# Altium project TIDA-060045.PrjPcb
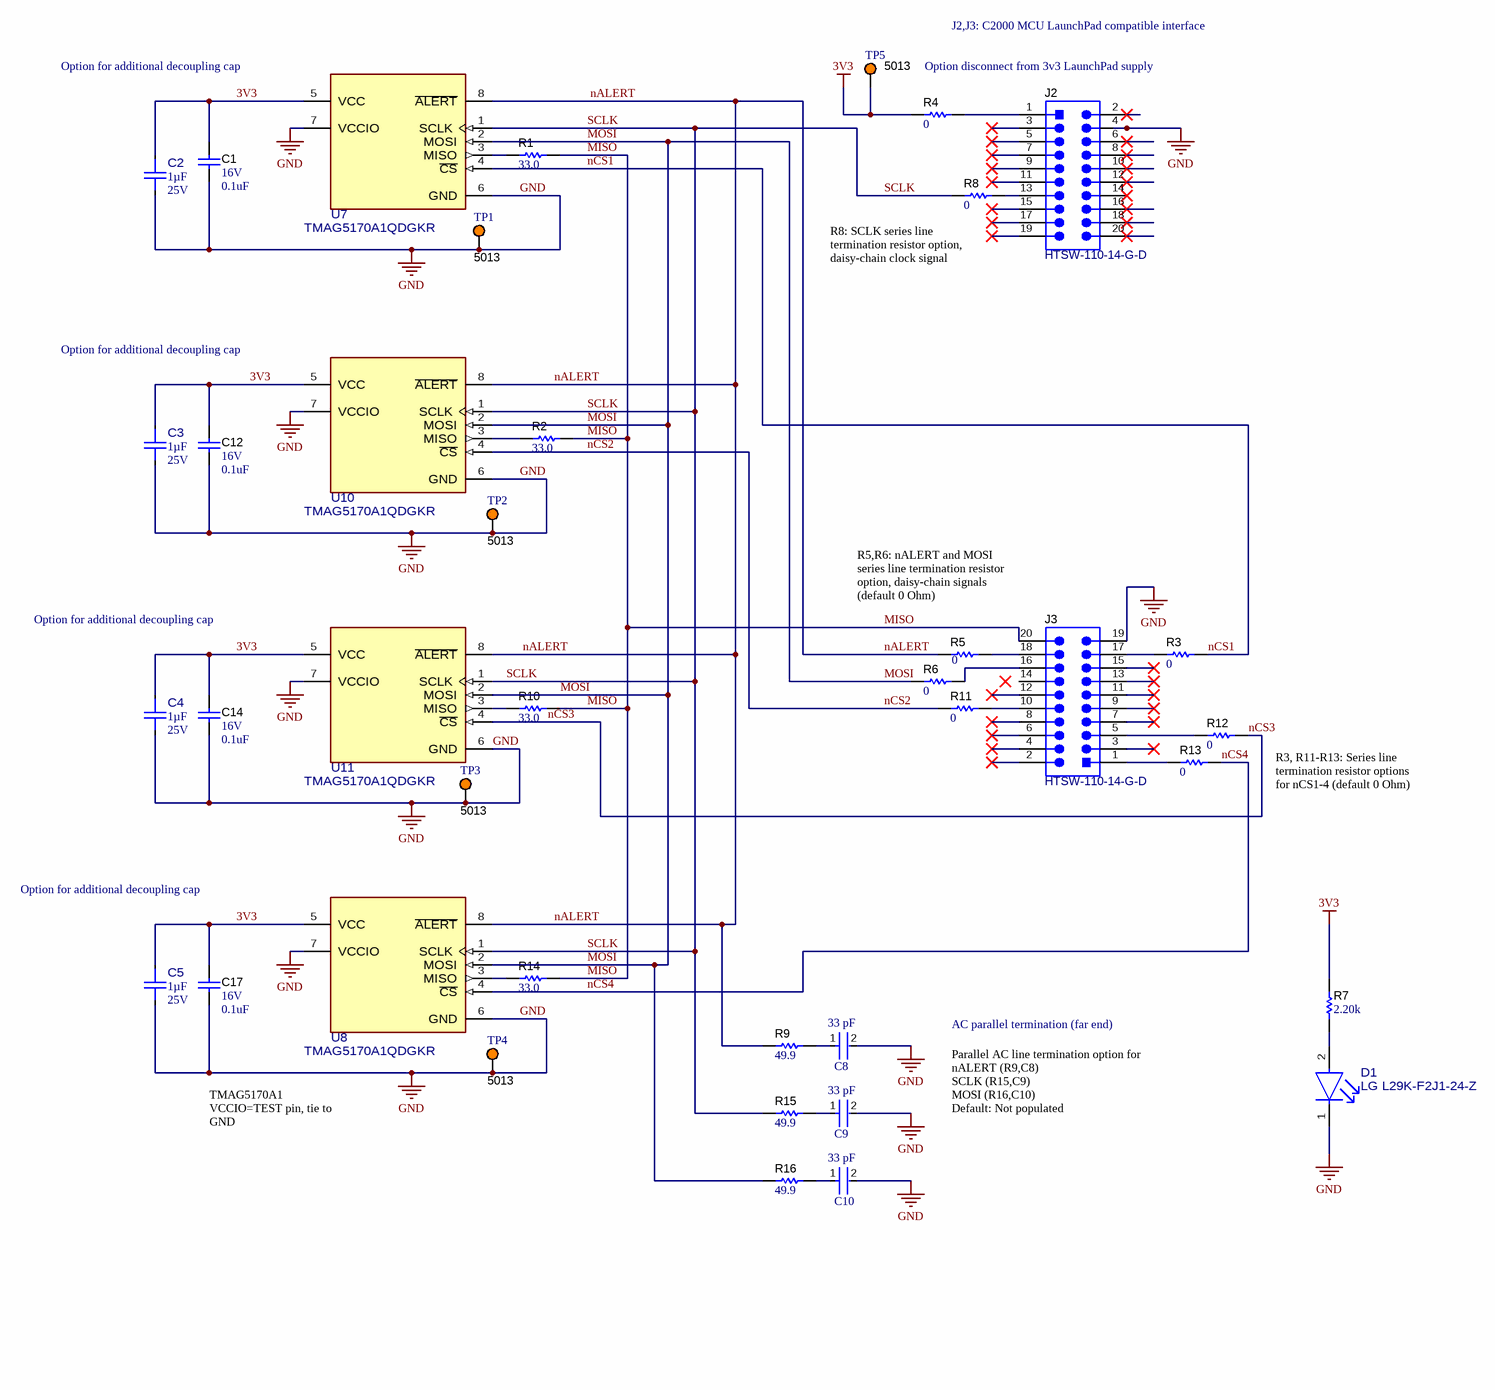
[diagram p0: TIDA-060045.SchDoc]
CopyrightYear: 2024; Drawn_By: Staebler/Vicario; PCB_Layout: Staebler/Vicario; PCB_Rev: E1.1; PRJ_Customer: Public Release; PRJ_Engineer: Staebler/Vicario; PRJ_Number: TIDA-060045; PRJ_Title: Linear Position Sensing TMAG5170; SCH_Rev: E1.1; TechSupport: N/A; TID: TIDA-060045
2 sheets, 50 parts. Net scope: global (net labels, ports and power ports of the same name join across sheets).
Board file: TIDA-060045.PcbDoc
Sheets:
  TIDA-060045.SchDoc
  TIDA-060045_Hardware.SchDoc

## Sheet TIDA-060045.SchDoc
size A2; Date: 11/16/2020; ApprovedBy: Not shown in title block; CheckedBy: Not shown in title block; Author: Ester Vicario Bravo; CompanyName: Texas Instruments; DrawnBy: Ester Vicario; Engineer: Ester Vicario Bravo; Organization: Texas Instruments; Address1: Haggerstrasse 1, Freising; Address2: Not shown in title block; Address3: Not shown in title block; Address4: Not shown in title block; DocumentNumber: 2; Revision: E1; SheetNumber: 2; SheetTotal: 3; PageSetup: Record=PageOptions¦CenterHorizontal=True¦CenterVertical=True¦PrintScale=1.00¦XCorrection=1.00¦YCorrection=1.00¦PrintKind=0¦BorderSize=5000000¦LeftOffset=0¦BottomOffset=0¦Orientation=2¦PaperLength=1000¦PaperWidth=1000¦Scale=100¦PaperSource=15¦PrintQuality=600¦MediaType=1¦DitherType=10¦PaperKind=Letter¦PrintScaleMode=1

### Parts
C1  VDC_V: 16V  ValueDisplayed: 0.1uF  [0402]  (hidden comment: C0402C104K4RACAUTO)
C2  Cap_F: 1µF  VDC_V: 25V  [FP-C1608X7R1E105K080AE_0603-MFG]  (hidden comment: C1608X7R1E105K080AE)
C3  Cap_F: 1µF  VDC_V: 25V  [FP-C1608X7R1E105K080AE_0603-MFG]  (hidden comment: C1608X7R1E105K080AE)
C4  Cap_F: 1µF  VDC_V: 25V  [FP-C1608X7R1E105K080AE_0603-MFG]  (hidden comment: C1608X7R1E105K080AE)
C5  Cap_F: 1µF  VDC_V: 25V  [FP-C1608X7R1E105K080AE_0603-MFG]  (hidden comment: C1608X7R1E105K080AE)
C8  value 33 pF  [FP-C0603C-CF-MFG]  (hidden comment: C0603C330J5GACTU)
C9  value 33 pF  [FP-C0603C-CF-MFG]  (hidden comment: C0603C330J5GACTU)
C10  value 33 pF  [FP-C0603C-CF-MFG]  (hidden comment: C0603C330J5GACTU)
C12  VDC_V: 16V  ValueDisplayed: 0.1uF  [0402]  (hidden comment: C0402C104K4RACAUTO)
C14  VDC_V: 16V  ValueDisplayed: 0.1uF  [0402]  (hidden comment: C0402C104K4RACAUTO)
C17  VDC_V: 16V  ValueDisplayed: 0.1uF  [0402]  (hidden comment: C0402C104K4RACAUTO)
D1  LG L29K-F2J1-24-Z  [FP-LG L29K-F2J1-24-Z_0603-MFG]
J2  HTSW-110-14-G-D  [Samtec_HTSW-110-14-x-D]
J3  HTSW-110-14-G-D  [Samtec_HTSW-110-14-x-D]
R1  ValueDisplayed: 33.0  [0402]  (hidden comment: RMCF0402FT33R0)
R2  ValueDisplayed: 33.0  [0402]  (hidden comment: RMCF0402FT33R0)
R3  ValueDisplayed: 0  [0603]  (hidden comment: RMCF0603ZT0R00)
R4  ValueDisplayed: 0  [0603]  (hidden comment: RMCF0603ZT0R00)
R5  ValueDisplayed: 0  [0603]  (hidden comment: RMCF0603ZT0R00)
R6  ValueDisplayed: 0  [0603]  (hidden comment: RMCF0603ZT0R00)
R7  ValueDisplayed: 2.20k  [0402]  (hidden comment: ERA2AEB222X)
R8  ValueDisplayed: 0  [0603]  (hidden comment: RMCF0603ZT0R00)
R9  ValueDisplayed: 49.9  [0603]  (hidden comment: M55342K12B49D9T)
R10  ValueDisplayed: 33.0  [0402]  (hidden comment: RMCF0402FT33R0)
R11  ValueDisplayed: 0  [0603]  (hidden comment: RMCF0603ZT0R00)
R12  ValueDisplayed: 0  [0603]  (hidden comment: RMCF0603ZT0R00)
R13  ValueDisplayed: 0  [0603]  (hidden comment: RMCF0603ZT0R00)
R14  ValueDisplayed: 33.0  [0402]  (hidden comment: RMCF0402FT33R0)
R15  ValueDisplayed: 49.9  [0603]  (hidden comment: M55342K12B49D9T)
R16  ValueDisplayed: 49.9  [0603]  (hidden comment: M55342K12B49D9T)
TP1  5013  [Keystone5013]
TP2  5013  [Keystone5013]
TP3  5013  [Keystone5013]
TP4  5013  [Keystone5013]
TP5  5013  [Keystone5013]
U7  TMAG5170A1QDGKR  [DGK0008A-MFG]
U8  TMAG5170A1QDGKR  [DGK0008A-MFG]
U10  TMAG5170A1QDGKR  [DGK0008A-MFG]
U11  TMAG5170A1QDGKR  [DGK0008A-MFG]

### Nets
3V3: C1.1 C2.1 C3.1 C4.1 C5.1 C12.1 C14.1 C17.1 R4.1 R7.2 TP5.1 U7.5(VCC) U8.5(VCC) U10.5(VCC) U11.5(VCC)
GND: C1.2 C2.2 C3.2 C4.2 C5.2 C8.2 C9.2 C10.2 C12.2 C14.2 C17.2 D1.1(CATHODE) J2.4 J3.19 TP1.1 TP2.1 TP3.1 TP4.1 U7.6(GND) U7.7(VCCIO) U8.6(GND) U8.7(VCCIO) U10.6(GND) U10.7(VCCIO) U11.6(GND) U11.7(VCCIO)
MISO: J3.20 R1.2 R2.2 R10.2 R14.2
MOSI: R6.1 R16.1 U7.2(MOSI) U8.2(MOSI) U10.2(MOSI) U11.2(MOSI)
nALERT: R5.1 R9.1 U7.8(~{ALERT}) U8.8(~{ALERT}) U10.8(~{ALERT}) U11.8(~{ALERT})
nCS1: R3.2 U7.4(~{CS})
nCS2: R11.1 U10.4(~{CS})
nCS3: R12.2 U11.4(~{CS})
nCS4: R13.2 U8.4(~{CS})
SCLK: R8.1 R15.1 U7.1(SCLK) U8.1(SCLK) U10.1(SCLK) U11.1(SCLK)
NetC8_1: C8.1 R9.2
NetC9_1: C9.1 R15.2
NetC10_1: C10.1 R16.2
NetD1_2: D1.2(ANODE) R7.1
NetJ2_1: J2.1 R4.2
NetJ2_13: J2.13 R8.2
NetJ3_1: J3.1 R13.1
NetJ3_5: J3.5 R12.1
NetJ3_10: J3.10 R11.2
NetJ3_16: J3.16 R6.2
NetJ3_17: J3.17 R3.1
NetJ3_18: J3.18 R5.2
NetR1_1: R1.1 U7.3(MISO)
NetR2_1: R2.1 U10.3(MISO)
NetR10_1: R10.1 U11.3(MISO)
NetR14_1: R14.1 U8.3(MISO)

Not connected (* = marked no-connect by the designer): J2 2* 3* 5* 6* 7* 8* 9* 10* 11* 12* 14* 15* 16* 17* 18* 19* 20*; J3 2* 3* 4* 6* 7* 8* 9* 11* 12* 13* 14 15*

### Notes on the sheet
- J2,J3: C2000 MCU LaunchPad compatible interface
- Option for additional decoupling cap
- Option disconnect from 3v3 LaunchPad supply
- (near R8) R8: SCLK series line termination resistor option, daisy-chain clock signal
- R5,R6: nALERT and MOSI series line termination resistor option, daisy-chain signals (default 0 Ohm)
- R3, R11-R13: Series line termination resistor options for nCS1-4 (default 0 Ohm)
- AC parallel termination (far end)
- TMAG5170A1 VCCIO=TEST pin, tie to GND
- Parallel AC line termination option for
  nALERT (R9,C8)
  SCLK (R15,C9)
  MOSI (R16,C10)
  Default: Not populated

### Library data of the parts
C1 C12 C14 C17 = CMP-0006237-2: CAP, CERM, 0.1 uF, 16 V, +/- 10%, X7R, AEC-Q200 Grade 1, 0402; Manufacturer: Kemet; TaMin_C: -55°C; Polarized: N; SizeAreaWB_mm2: 3; Value1: Unknown; U/M: EA; Value: 0.1uF; TaMax_C: 125°C; SizeZ_mm: 0.6; SizeX_mm: 1; SizeY_mm: 0.5; AEC Qualified: Y; Cap_F: 100nF; AEC Category: Q200
C2-C5 = CMP-0116394-1: C Series 0603 1 uF 25 V ±10 %Tolerance X7R SMT Multilayer Ceramic Capacitor; Manufacturer: TDK; AEC Qualified: No; SizeZ_mm: 0.95mm; TempCo: 15%; Tolerance_%: 10%; ValueDisplayed: 1uF; Value: 1µF
C8-C10 = CMP-2006-03168-3: Capacitor; Ceramic; Cap; 33.0pF; Tol 5%; SMT; Vol-Rtg 50V; C0G; Tape and Reel; Manufacturer: KEMET; Tolerance: 0.05; Temperature Coefficient: 30ppm/°C; Automotive Grade: Grade 1
D1 = CMP-0088492-1: Green 570nm LED Indication - Discrete 1.7V 0603 (1608 Metric); Manufacturer: Osram; Tjmax_C: 110°C; Angle: 160°; LambdaP: 572nm; Vr_V: 12V; SizeZ_mm: 0.67mm; Luminous Intensity: 1.4-5.6mcd; Forward Current: 2mA; Led Orientation: Top View; AEC Qualified: No
J2 J3 = CMP-0082589-1: Header, 2.54mm, 10x2, Gold, TH; Manufacturer: Samtec; Pitch_mm: 2.54; Gender: Male; Cert_UL: Y; Shrouded: N; Row_Count: 2
R1 R2 R10 R14 = CMP-0026759-1: RES, 33.0, 1%, 0.063 W, AEC-Q200 Grade 0, 0402; Manufacturer: Stackpole Electronics Inc; Power_W: 63mW; TempCo: 100 ppm/C; Value_Code: 33R0; U/M: EA; Value: 33.0; Res_ohm: 33; SizeX_mm: 1; SizeY_mm: 0.5; SizeZ_mm: 0.6; Value2: 0.063W; AEC Qualified: Y; VDC_V: 50V; AEC Grade: 0; AEC Category: Q200
R3-R6 R8 R11-R13 = CMP-0023343-3: RES, 0, 1%, 0.1 W, AEC-Q200 Grade 0, 0603; Manufacturer: Stackpole Electronics Inc; Power_W: 100mW; TempCo: ppm/C; U/M: EA; Value: 0; SizeX_mm: 1.6; SizeY_mm: 0.8; SizeZ_mm: 1; Value2: 0.1W; SizeArea_mm2: 1.28; AEC Qualified: Y; AEC Category: Q200
R7 = CMP-0074667-1: RES, 2.20 k, 0.1%, 0.0625 W, AEC-Q200 Grade 0, 0402; Manufacturer: Panasonic; Power_W: 62.5mW; TempCo: 25 ppm/C; Value_Code: 2k20; U/M: EA; Value: 2.20k; Res_ohm: 2.2k; SizeX_mm: 1.0; SizeY_mm: 0.5; SizeZ_mm: 0.6; AEC Qualified: Y; VDC_V: 50V; AEC Grade: 0; AEC Category: Q200
R9 R15 R16 = CMP-0080492-1: RES, 49.9, 1%, 0.1 W, 0603; Manufacturer: TT Electronics/IRC; Power_W: 100mW; TempCo: 100 ppm/C; SizeAreaWB_mm2: 4.68; Value_Code: 49R9; Value: 49.9; EIA_Code: E96; SizeX_mm: 1.6; SizeY_mm: 0.8; SizeZ_mm: 1; Value2: 0.1W; SizeArea_mm2: 1.28; AEC Qualified: N; AEC Category: Q200
TP1-TP5 = CMP-0055150-1: Test Point, Multipurpose, Orange, TH; Manufacturer: Keystone; CNHeader: FALSE; Green_Lifecycle: Active; Green_REACh: Passed; ContactFinish: Silver; CT: TRUE
U7 U8 U10 U11 = CMP-0088287-1: 3-Axis Linear Hall Effect Sensor With SPI Interface; Manufacturer: Texas Instruments; TJmax_C: +170°C; SizeZ_mm: 1.1mm; Operating Supply Current: 0.000005-4mA; Standoff Height: 0.05mm; Min Supply Voltage: 1.65V; Max Supply Voltage: 5.5V; AEC Grade: Grade 0; AEC Qualified: Yes

## Sheet TIDA-060045_Hardware.SchDoc
size 431 x 279 mm; Date: Not shown in title block; ApprovedBy: Not shown in title block; CheckedBy: Not shown in title block; Author: Not shown in title block; CompanyName: Not shown in title block; Engineer: Not shown in title block; Organization: Not shown in title block; Address1: Not shown in title block; Address2: Not shown in title block; Address3: Not shown in title block; Address4: Not shown in title block; DocumentNumber: 3; Revision: Use project parameter SCH_Rev; SheetNumber: 3; SheetTotal: 3; PageSetup: Record=PageOptions¦CenterHorizontal=True¦CenterVertical=True¦PrintScale=1.00¦XCorrection=1.00¦YCorrection=1.00¦PrintKind=0¦BorderSize=5000000¦LeftOffset=0¦BottomOffset=0¦Orientation=2¦PaperLength=1000¦PaperWidth=1000¦Scale=100¦PaperSource=15¦PrintQuality=600¦MediaType=1¦DitherType=10¦PaperKind=Letter¦PrintScaleMode=1
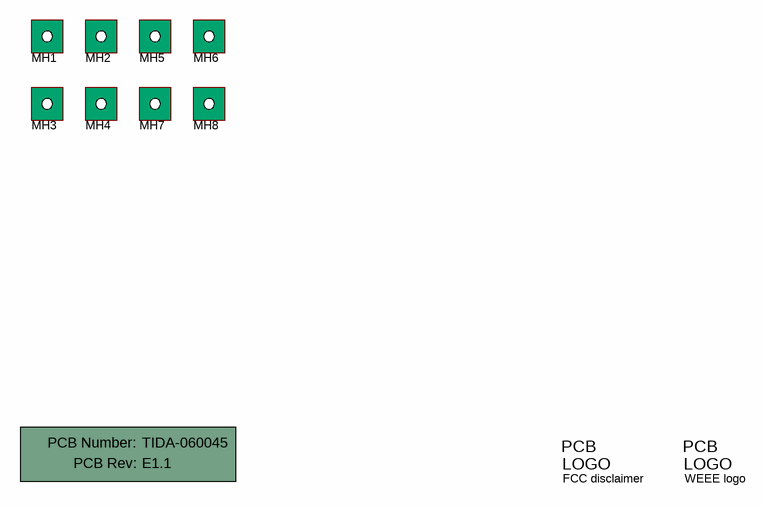
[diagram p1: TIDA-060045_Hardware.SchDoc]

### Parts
!PCB1  Printed Circuit Board  (value not drawn)  (mechanical)
Logo3  FCC disclaimer  [FCC_disclaimer]  (no BOM)
Logo4  WEEE logo  [WEEE_Minimum]  (no BOM)
MH1  MTG_NoPads  [NPTH125mil]  (value not drawn)  (no BOM)
MH2  MTG_NoPads  [NPTH125mil]  (value not drawn)  (no BOM)
MH3  MTG_NoPads  [NPTH125mil]  (value not drawn)  (no BOM)
MH4  MTG_NoPads  [NPTH125mil]  (value not drawn)  (no BOM)
MH5  MTG_NoPads  [NPTH125mil]  (value not drawn)  (no BOM)
MH6  MTG_NoPads  [NPTH125mil]  (value not drawn)  (no BOM)
MH7  MTG_NoPads  [NPTH125mil]  (value not drawn)  (no BOM)
MH8  MTG_NoPads  [NPTH125mil]  (value not drawn)  (no BOM)

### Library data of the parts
!PCB1 = CMP-0003618-2: Manufacturer: Any; PartNumber: TIDA-060045
Logo3 = CMP-0074847-1: FCC_disclaimer; Library Reference: Logo
Logo4 = CMP-0074769-1
MH1-MH8 = CMP-0078424-2: PCB Mounting Hole, No Pad; Manufacturer: Any; Key: Mounting Hole (non-standard) No Pad

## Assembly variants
001: not fitted C2 C2 C3 C3 C3 C4 C4 C4 C5 C5 C7 C8 C9 C10 FID1 FID2 FID3 J4 Logo1 R4 R5 R6 R8 R9 R9 R15 R15 R16 R16 TP1 TP2 TP3 TP4 TP5 U1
